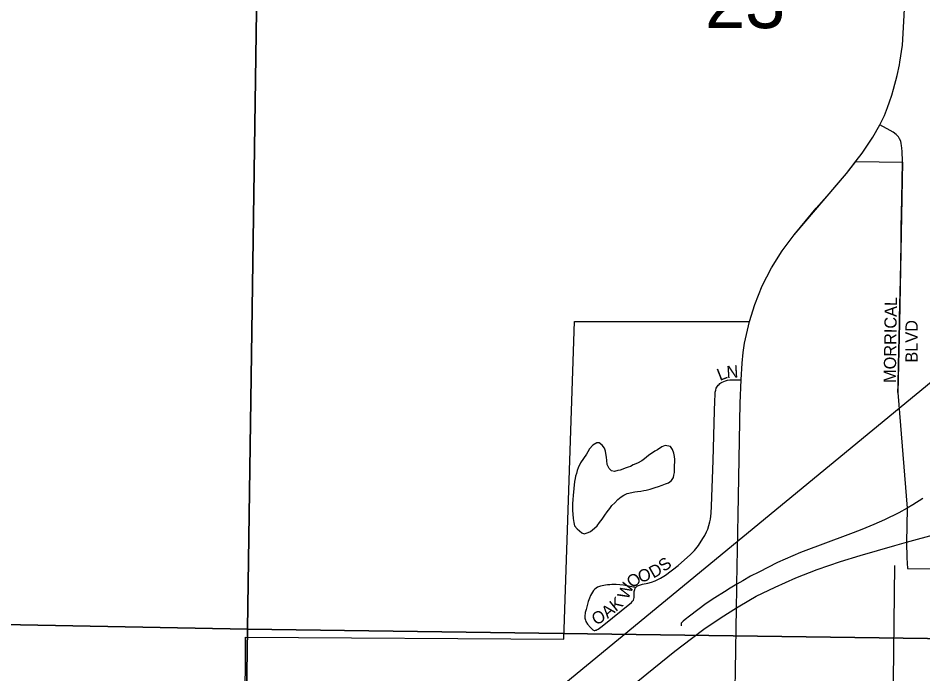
# Model space of a CAD drawing. Extents: x 1587405 to 1714697, y 1028970 to 1155083.
# Drawn here: x 1639431 to 1643143, y 1103007 to 1105700 of the extents above; entities that cross this region are included whole.
import ezdxf

# ---------------------------------------------------------------- set-up
doc = ezdxf.new("R2010")
doc.units = 0
for name, color, linetype in [('GM_X_City_Street', 7, 'Continuous'), ('GM_X_City_Street_Text', 7, 'Continuous'), ('GM_X_Corporation', 7, 'Continuous'), ('GM_X_County_Road', 7, 'Continuous'), ('GM_X_Interchange_Ramps', 7, 'Continuous'), ('GM_X_Interstate_Route', 7, 'Continuous'), ('GM_X_Minor_Lake', 7, 'Continuous'), ('GM_X_Rail_Line', 7, 'Continuous'), ('GM_X_Section', 7, 'Continuous'), ('GM_X_Section_Text', 7, 'Continuous')]:
    doc.layers.add(name, color=color, linetype=linetype)

msp = doc.modelspace()

# ---------------------------------------------------------------- linework, layer by layer
at = {"layer": 'GM_X_City_Street'}
for points in [[(1642397.9, 1104214.4), (1642400.9, 1104283.3), (1642404.9, 1104327.4), (1642410.8, 1104365.1), (1642431, 1104453.6)], [(1643039.7, 1104163), (1643040.9, 1104196), (1643042.9, 1104274.1), (1643046.5, 1104446.6)], [(1641963, 1103362.3), (1641915.2, 1103371.7), (1641900.2, 1103372.9), (1641884.8, 1103373.6), (1641866.3, 1103373.6), (1641858.6, 1103373.5), (1641848.3, 1103373.2), (1641841, 1103372.2), (1641834.4, 1103370.8), (1641827.3, 1103369.1), (1641820.6, 1103367.2), (1641815.8, 1103365.6), (1641808.4, 1103362.9), (1641802.4, 1103359.5), (1641797.5, 1103355.5), (1641791.9, 1103349.5), (1641787.3, 1103343.1), (1641783.1, 1103336.5), (1641779.5, 1103329.2), (1641774.6, 1103317.5), (1641769.7, 1103303.9), (1641760.8, 1103271.6), (1641757.7, 1103259.8), (1641756.8, 1103254.3), (1641756.3, 1103248.9), (1641755.9, 1103243.8), (1641756.1, 1103239.5), (1641756.5, 1103235.9), (1641757.2, 1103231.8), (1641758.5, 1103227.6), (1641760.5, 1103222.8), (1641767.3, 1103212.1), (1641779, 1103197.4), (1641789.3, 1103188.7), (1641793.7, 1103186), (1641796.7, 1103185.8), (1641799.9, 1103186.5), (1641802.9, 1103187.3), (1641806.7, 1103189), (1641810.4, 1103191.5), (1641827, 1103203.5), (1641947.6, 1103300.6), (1641952, 1103305.8), (1641955.3, 1103310.5), (1641956.8, 1103315.7), (1641957.7, 1103321.5), (1641957.9, 1103329.6), (1641958, 1103338.5), (1641958.3, 1103342.6), (1641958.6, 1103345.8), (1641959.2, 1103349.3), (1641960.5, 1103353.1), (1641961.5, 1103355.9), (1641962.8, 1103359), (1641964, 1103361.1), (1641965.4, 1103363), (1641967.3, 1103364.8), (1641969.4, 1103366.5), (1641971.9, 1103368.2), (1641975.5, 1103370.2), (1641980.2, 1103372.2), (1641983.9, 1103373.4), (1641992.7, 1103375.5), (1642014.6, 1103380.4), (1642029.6, 1103384.4), (1642043.9, 1103389), (1642067, 1103400.6), (1642087.1, 1103412.7), (1642139.4, 1103452.5), (1642189, 1103497.4), (1642205.3, 1103514), (1642222.2, 1103534.1), (1642240.7, 1103562.5), (1642248.2, 1103576.1), (1642255, 1103590.5), (1642260.2, 1103601.9), (1642264.4, 1103616.2), (1642268.3, 1103631.2), (1642270.9, 1103642.5), (1642272.6, 1103654.6), (1642273.8, 1103667.3), (1642275.8, 1103695.9), (1642282.5, 1103884), (1642288, 1104086.7), (1642288.7, 1104127.1), (1642290.3, 1104154.9), (1642291.2, 1104164.5), (1642293.1, 1104172.3), (1642295.4, 1104180.1), (1642299.7, 1104188.3), (1642302.6, 1104192.5), (1642306.5, 1104195.8), (1642310.1, 1104199), (1642314, 1104202), (1642318.8, 1104204.9), (1642325.7, 1104208.2), (1642333.2, 1104210.4), (1642341.3, 1104212.7), (1642350.2, 1104214), (1642364.4, 1104215), (1642397.9, 1104214.4)], [(1642372.1, 1102947.6), (1642373.7, 1103021), (1642378.1, 1103278.4), (1642379.6, 1103354.9), (1642380.1, 1103375.1), (1642384.8, 1103660.5), (1642393.6, 1104119.3), (1642397.9, 1104214.4)], [(1643020.9, 1102938.6), (1643021.7, 1102982.6), (1643027.6, 1103451.7)]]:
    msp.add_lwpolyline(points, dxfattribs=at)
at = {"layer": 'GM_X_Corporation'}
msp.add_lwpolyline([(1640358.2, 1101881.3), (1640363.2, 1103157.7), (1641670.2, 1103149.6), (1641714.2, 1104454.5), (1642431, 1104453.6), (1642452.9, 1104524.3), (1642483.7, 1104600.8), (1642521.4, 1104674.1), (1642565.3, 1104743.8), (1642614.7, 1104809.7), (1642705.4, 1104919.3), (1642779.7, 1105003.9), (1642829.9, 1105061.1), (1642867.9, 1105111.2), (1643058.8, 1105108.6), (1643046.5, 1104446.6), (1643039.7, 1104163), (1643078.7, 1103688), (1643077.5, 1103615.7), (1643076.2, 1103547.9), (1643076.5, 1103483.7), (1643079.9, 1103439.9), (1643222.7, 1103438.7)], dxfattribs=at)
at = {"layer": 'GM_X_County_Road'}
for points in [[(1642966.4, 1105261.2), (1642979, 1105286.3), (1642985.1, 1105300.4), (1642997.6, 1105333.1), (1643005.6, 1105356), (1643015.4, 1105383.7), (1643022.7, 1105407.3), (1643037.5, 1105464.1), (1643047, 1105508.2), (1643048.5, 1105518.5), (1643058.8, 1105589), (1643066.6, 1105710.1), (1643067.5, 1105739), (1643070, 1105788.2), (1643078.9, 1106205.4), (1643091, 1107008.8), (1643095.4, 1107289.3)], [(1642431, 1104453.6), (1642452.9, 1104524.3), (1642483.7, 1104600.8), (1642521.4, 1104674.1), (1642565.3, 1104743.8), (1642614.7, 1104809.7), (1642829.9, 1105061.1), (1642869.4, 1105113.1), (1642893.7, 1105145.1), (1642937.5, 1105210.4), (1642966.4, 1105261.2)], [(1643046.5, 1104446.6), (1643046.8, 1104469.6), (1643050.4, 1104627), (1643053.8, 1104771.3), (1643054.2, 1104840.2), (1643056, 1104958.3), (1643058.8, 1105108.6), (1643058.8, 1105124.1), (1643058.3, 1105139), (1643057.3, 1105152.4), (1643057, 1105165.3), (1643055.5, 1105176), (1643054.4, 1105184.4), (1643051.7, 1105195), (1643047.5, 1105204.2), (1643042.5, 1105212.5), (1643037.9, 1105217.4), (1643033.8, 1105221.7), (1643021.2, 1105231.5), (1643008.2, 1105238.6), (1642966.4, 1105261.2)]]:
    msp.add_lwpolyline(points, dxfattribs=at)
at = {"layer": 'GM_X_Interchange_Ramps'}
msp.add_lwpolyline([(1643143.2, 1103727), (1643101.7, 1103700.7), (1643078.7, 1103688), (1643044.4, 1103669), (1642985.5, 1103640.1), (1642941.8, 1103620.2), (1642892.1, 1103600.3), (1642856.9, 1103585.9), (1642823.7, 1103573.7), (1642754.5, 1103548.5), (1642640.1, 1103505.9), (1642545.8, 1103464), (1642470.4, 1103425.5), (1642436.3, 1103408), (1642403.8, 1103389.4), (1642380.1, 1103375.1), (1642352.8, 1103358.6), (1642329.3, 1103344.6), (1642289.1, 1103319.5), (1642254.4, 1103296.3), (1642185.4, 1103244.5), (1642168.2, 1103231.1), (1642159.4, 1103223.7), (1642154.3, 1103218.7), (1642151.8, 1103215.3), (1642150.7, 1103212), (1642150.5, 1103209.1), (1642150.7, 1103205.1)], dxfattribs=at)
at = {"layer": 'GM_X_Interstate_Route'}
for points in [[(1643076.2, 1103547.9), (1643201, 1103582.7), (1643310.6, 1103616.6), (1643403.4, 1103648.8), (1643428.5, 1103657.7), (1643507.6, 1103685.9), (1643618.7, 1103737.5), (1643651.9, 1103753.5), (1643681.7, 1103768.8)], [(1642010.1, 1103007.4), (1642124.7, 1103100.3), (1642193, 1103152.4), (1642243.7, 1103190.3), (1642314.7, 1103238.3), (1642378.1, 1103278.4), (1642391.8, 1103287.1), (1642458.7, 1103326.3), (1642536.5, 1103363.5), (1642621.7, 1103401.5), (1642709, 1103435.3), (1642804.9, 1103469.2), (1642885, 1103493.2), (1643027.2, 1103534.1), (1643076.2, 1103547.9)], [(1641031, 1101864.1), (1641049.2, 1101901.3), (1641093.8, 1101987.9), (1641143.8, 1102073.8), (1641186.4, 1102143.5), (1641240.5, 1102226), (1641298.6, 1102309.2), (1641358.1, 1102385), (1641423, 1102462.8), (1641486.5, 1102537.2), (1641542.6, 1102598.8), (1641617.7, 1102670.5), (1641685.3, 1102732.8), (1641771.8, 1102810.6), (1641958.4, 1102965.6), (1642010.1, 1103007.4)]]:
    msp.add_lwpolyline(points, dxfattribs=at)
at = {"layer": 'GM_X_Minor_Lake'}
for points in [[(1641738.4, 1103873.8), (1641737.3, 1103871.5), (1641728.9, 1103853.6), (1641724.7, 1103841.7), (1641722.4, 1103829.7), (1641718.2, 1103819.7), (1641716, 1103809.7), (1641713.8, 1103797.7), (1641708.6, 1103739.7), (1641706.2, 1103723.7), (1641705.9, 1103705.6), (1641705.5, 1103689.6), (1641705.3, 1103677.6), (1641707, 1103663.5), (1641708.7, 1103645.4), (1641710.3, 1103629.3), (1641714.1, 1103615.2), (1641723.9, 1103602.9), (1641733.7, 1103594.7), (1641743.6, 1103586.5), (1641753.5, 1103582.3), (1641769.7, 1103588), (1641779.8, 1103591.8), (1641796.2, 1103605.5), (1641806.4, 1103615.3), (1641816.7, 1103629.1), (1641827, 1103643), (1641837.4, 1103658.8), (1641847.7, 1103672.6), (1641858, 1103686.5), (1641866.3, 1103698.3), (1641878.5, 1103710.1), (1641890.9, 1103723.9), (1641905.1, 1103733.7), (1641915.3, 1103741.5), (1641929.5, 1103747.2), (1641961.7, 1103754.6), (1641971.8, 1103756.4), (1641985.9, 1103758.1), (1641997.9, 1103759.9), (1642008, 1103761.7), (1642024.1, 1103765.3), (1642044.4, 1103773), (1642058.5, 1103776.7), (1642072.6, 1103782.4), (1642086.8, 1103788.1), (1642098.9, 1103791.9), (1642111.2, 1103801.7), (1642119.4, 1103813.6), (1642121.6, 1103823.5), (1642123.8, 1103833.5), (1642124.2, 1103851.6), (1642124.5, 1103865.6), (1642124.7, 1103875.6), (1642124.9, 1103887.7), (1642123.2, 1103899.8), (1642121.5, 1103913.8), (1642115.7, 1103928), (1642107.9, 1103940.2), (1642086, 1103944.6), (1642071.8, 1103938.9), (1642053.5, 1103927.2), (1642043.4, 1103921.4), (1642016.9, 1103903.9), (1642000.6, 1103890.2), (1641990.4, 1103882.4), (1641972.1, 1103872.7), (1641953.9, 1103865.1), (1641943.8, 1103859.3), (1641933.7, 1103855.4), (1641921.5, 1103851.7), (1641911.4, 1103847.9), (1641901.3, 1103844.1), (1641891.2, 1103842.3), (1641877.1, 1103838.6), (1641865.1, 1103840.8), (1641855.3, 1103851), (1641847.6, 1103867.2), (1641845.9, 1103883.3), (1641844.2, 1103897.4), (1641842.5, 1103911.5), (1641840.7, 1103921.5), (1641836.9, 1103933.6), (1641827.1, 1103945.9), (1641815.3, 1103956.2), (1641805.3, 1103956.4), (1641789, 1103946.7), (1641774.6, 1103930.9), (1641768.4, 1103919), (1641762.2, 1103909.1), (1641738.4, 1103873.8)], [(1642086.8, 1103788.1), (1642098.9, 1103791.9), (1642111.2, 1103801.7), (1642119.4, 1103813.6), (1642121.6, 1103823.5), (1642123.8, 1103833.5), (1642124.2, 1103851.6), (1642124.5, 1103865.6), (1642124.7, 1103875.6), (1642124.9, 1103887.7), (1642123.2, 1103899.8), (1642121.5, 1103913.8), (1642115.7, 1103928), (1642107.9, 1103940.2), (1642086, 1103944.6), (1642071.8, 1103938.9), (1642053.5, 1103927.2), (1642043.4, 1103921.4), (1642016.9, 1103903.9), (1642000.6, 1103890.2), (1641990.4, 1103882.4), (1641972.1, 1103872.7), (1641953.9, 1103865.1), (1641943.8, 1103859.3), (1641933.7, 1103855.4), (1641921.5, 1103851.7), (1641911.4, 1103847.9), (1641901.3, 1103844.1), (1641891.2, 1103842.3), (1641877.1, 1103838.6), (1641865.1, 1103840.8), (1641855.3, 1103851), (1641847.6, 1103867.2), (1641845.9, 1103883.3), (1641844.2, 1103897.4), (1641842.5, 1103911.5), (1641840.7, 1103921.5), (1641836.9, 1103933.6), (1641827.1, 1103945.9), (1641815.3, 1103956.2), (1641805.3, 1103956.4), (1641789, 1103946.7), (1641774.6, 1103930.9), (1641768.4, 1103919), (1641762.2, 1103909.1), (1641738.4, 1103873.8)], [(1641738.4, 1103873.8), (1641737.3, 1103871.5), (1641728.9, 1103853.6), (1641724.7, 1103841.7), (1641722.4, 1103829.7), (1641718.2, 1103819.7), (1641716, 1103809.7), (1641713.8, 1103797.7), (1641708.6, 1103739.7), (1641706.2, 1103723.7), (1641705.9, 1103705.6), (1641705.5, 1103689.6), (1641705.3, 1103677.6), (1641707, 1103663.5), (1641708.7, 1103645.4), (1641710.3, 1103629.3), (1641714.1, 1103615.2), (1641723.9, 1103602.9), (1641733.7, 1103594.7), (1641743.6, 1103586.5), (1641753.5, 1103582.3), (1641769.7, 1103588), (1641779.8, 1103591.8), (1641796.2, 1103605.5), (1641806.4, 1103615.3), (1641816.7, 1103629.1), (1641827, 1103643), (1641837.4, 1103658.8), (1641847.7, 1103672.6), (1641858, 1103686.5), (1641866.3, 1103698.3), (1641878.5, 1103710.1), (1641890.9, 1103723.9), (1641905.1, 1103733.7), (1641915.3, 1103741.5), (1641929.5, 1103747.2), (1641961.7, 1103754.6), (1641971.8, 1103756.4), (1641985.9, 1103758.1), (1641997.9, 1103759.9), (1642008, 1103761.7), (1642024.1, 1103765.3), (1642044.4, 1103773), (1642058.5, 1103776.7), (1642072.6, 1103782.4), (1642086.8, 1103788.1)]]:
    msp.add_lwpolyline(points, dxfattribs=at)
at = {"layer": 'GM_X_Rail_Line'}
for points in [[(1641894.6, 1103150.5), (1644669.1, 1105434.7), (1647210.1, 1107518)], [(1629314.4, 1092809.9), (1631806.5, 1094856.6), (1635602.9, 1097976.6), (1637660.3, 1099664.7), (1641894.6, 1103150.5)]]:
    msp.add_lwpolyline(points, dxfattribs=at)
at = {"layer": 'GM_X_Section'}
for points in [[(1635128.6, 1108536.3), (1640448.7, 1108458.5), (1640371.5, 1103190.4), (1635067.7, 1103292.1)], [(1640448.7, 1108458.5), (1645734.9, 1108387.2), (1645653.7, 1103119), (1640371.5, 1103190.4)], [(1640371.5, 1103190.4), (1640291.9, 1097896.4), (1634954.2, 1097996.5), (1635067.7, 1103292.1)], [(1645653.7, 1103119), (1645545.8, 1097805.3), (1640291.9, 1097896.4), (1640371.5, 1103190.4)]]:
    msp.add_lwpolyline(points, close=True, dxfattribs=at)

# ---------------------------------------------------------------- texts
at = {"layer": 'GM_X_City_Street_Text'}
for s, rotation, p in [('MORRICAL', 89.2271, (1643031.8, 1104201.5)), ('BLVD', 90, (1643121.3, 1104285.3)), ('N', 3.7617, (1642338.7, 1104221.4)), ('L', 21.1925, (1642309.8, 1104209.6)), ('D', 29.8485, (1642037.2, 1103398.2)), ('S', 37.6738, (1642081.5, 1103424.3)), ('O', 14.6512, (1641981.2, 1103381.6)), ('W', 66.4709, (1641932.8, 1103309.3)), ('O', 38.5096, (1641951.7, 1103356.7)), ('K', 39.1479, (1641883, 1103261)), ('A', 40.285, (1641849.7, 1103232.7)), ('O', 27.2883, (1641800.3, 1103205.7))]:
    msp.add_text(s, height=50, rotation=rotation, dxfattribs=at).set_placement(p)
at = {"layer": 'GM_X_Section_Text'}
msp.add_text('23', height=221, rotation=0, dxfattribs=at).set_placement((1642249.2, 1105658.4))

doc.saveas('drawing.dxf')
